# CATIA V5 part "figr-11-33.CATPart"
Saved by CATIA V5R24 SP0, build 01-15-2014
Part number: Part1
Bounding box of the stored display mesh (mm): x -120 to 40, y -443 to 443, z -443 to 443
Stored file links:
  D:\KAVITA\CATIA V5-6R2014 Project_ Kavita\CATIA V5-6R2014_partfiles\Partfiles\c11_catia_v5-6r2014_prt\figr-11-33.CATPart
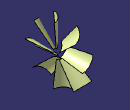
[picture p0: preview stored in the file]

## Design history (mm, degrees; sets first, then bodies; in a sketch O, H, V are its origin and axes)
Set1
  Plane1: type Offset, RefPlane xy-plane, Offset 443
  Sketch1 on Plane1, origin (0, 0, 443), H (1, 0, 0), V (0, 1, 0)
    arc A1 centre (51.3551, -160.9813) radius 171.358 from (40, 10) to (-120, -160) ccw
  Loft1: Sections (Sketch3; Sketch1)
  Sketch2 on zx-plane, origin (0, 0, 0), H (-1, 0, 0), V (0, 0, 1)
    line L1 (-270, 0) -> (280, 0)
    point P1 (-270, 0)
    coincidence: P1 H
    horizontal: L1 H
  Rotate1: ToTransfor Loft1, Axis Sketch2, Angle 45
  Rotate2: ToTransfor Loft1, Axis Sketch2, Angle 90 {= Rotate1.Angle * 2}
  Rotate3: ToTransfor Loft1, Axis Sketch2, Angle 135 {= Rotate1.Angle * 3}
  Rotate4: ToTransfor Loft1, Axis Sketch2, Angle 180 {= Rotate1.Angle * 4}
  Rotate5: ToTransfor Loft1, Axis Sketch2, Angle 225 {= Rotate1.Angle * 5}
  Rotate6: ToTransfor Loft1, Axis Sketch2, Angle 270 {= Rotate1.Angle * 6}
  Rotate7: ToTransfor Loft1, Axis Sketch2, Angle 315 {= Rotate1.Angle * 7}
  Rotate8: ToTransfor Loft1, Axis Sketch2, Angle 360 {= Rotate1.Angle * 8}
  Rotate9: ToTransfor Loft1, Axis Sketch2, Angle 405 {= Rotate1.Angle * 9}
Body1 (main body)
  Sketch3 on Plane2, origin (0, 0, 67), H (1, 0, 0), V (0, 1, 0)
    point P1 (-100, 0)
    arc A1 centre (50, -150) radius 158.1139 from (0, 0) to (-100, -100) ccw
Set2
  Plane2: type Offset, RefPlane xy-plane, Offset 67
